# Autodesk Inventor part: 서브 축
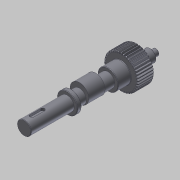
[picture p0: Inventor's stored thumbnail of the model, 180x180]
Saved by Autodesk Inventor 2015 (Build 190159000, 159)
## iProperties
Created: 2016-02
Part Number: 서브 축
Material: 강철, 연강
Document SubType Name: Modeling
Designer: mdu
Categories: <?xml version="1.0" encoding="UTF-16"?> <MemberInstance><Categories><FamilyTemplate><FamilyTemplateParameter ValueType="xs:double" Id="1" ObjectReferenceKey="da
Density: 7.86 g/cm^3
Mass: 504.229 g
Surface Area: 165.255 cm^2
Volume: 64.1512 cm^3
Appearance: 강철
CustomPartVersion: 1
Author: mdu
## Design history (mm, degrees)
sketch "Sketch1"
  geometry: C1 r 21 at (0, 0)
  constraints: 1 centre point
  dimensions: "d0" = 42 diameter of C1 (= da_da)
extrude "Extrusion1" new body sketch "Sketch1" distance "d1" = 20 (= da_b); taper "d2" = 0 deg
workplane "Work Plane2"
feature "피치 지름" dims "d4" = 10, "d5" = 0
workplane "Work Plane8"
workplane "Work Plane9"
chamfer "모따기1" distance "d49" = 1; stored, may be unused: second distance "d50" = 2, angle "d51" = 45 deg
sketch "스케치3"
  geometry: C1 r 12.5 at (0, 0); 1 further point
  constraints: 1 centre point, 1 coincident
  dimensions: "d52" = 25 diameter of C1
extrude "돌출2" join sketch "스케치3" distance "d53" = 16; taper "d54" = 0 deg
sketch "스케치4"
  geometry: C1 r 8.5 at (0, 0); 1 further point
  constraints: 1 centre point, 1 coincident
  dimensions: "d55" = 17 diameter of C1
extrude "돌출3" join sketch "스케치4" distance "d56" = 103; taper "d57" = 0 deg
sketch "스케치5"
  geometry: C1 r 7.5 at (0, 0); 1 further point
  constraints: 1 centre point, 1 coincident
  dimensions: "d62" = 15 diameter of C1
extrude "돌출4" join sketch "스케치5" distance "d63" = 16; taper "d64" = 0 deg
sketch "스케치6"
  geometry: C1 r 4 at (0, 0); 1 further point
  constraints: 1 centre point, 1 coincident
  dimensions: "d65" = 8 diameter of C1
extrude "돌출5" join sketch "스케치6" distance "d66" = 7; taper "d67" = 0 deg
chamfer "모따기2" distance "d58" = 0.5; stored, may be unused: second distance "d59" = 2, angle "d60" = 45 deg
fillet "모깎기1" dims "d61" = 0.5
feature "스퍼 기어" dims "da_b" = 20, "da_d" = 40, "da_aw" = 31, "da_da" = 42, "da_df" = 37.5, "da_dw" = 40, angle "da_beta" = 0 deg, "da_lefttooth" = 0, "da_righttooth" = 0
node "작업 평면11"
sketch "스케치7"
  geometry: C1 r 8.5 at (0, 0) reference; C2 r 11.5 at (0, 3); 1 further point
  constraints: 1 centre point, 1 tangent, 1 vertical alignment
  dimensions: "d71" = 3 distance of C2.centre point (0, 0); "d72" = 23 diameter of C2 (derived)
extrude "돌출6" join sketch "스케치7" stored distance "d73" = 20; taper "d74" = 0 deg
node "작업 평면12"
sketch "스케치8"
  geometry: C1 r 12.5 at (0, 0) reference; 1 further point
extrude "돌출7" join sketch "스케치8" distance "d76" = 5; taper "d77" = 0 deg
chamfer "모따기3" distance "d78" = 0.5; stored, may be unused: second distance "d79" = 2, angle "d80" = 45 deg
sketch "스케치9"
  geometry: L1 (-8.5, 86)-(-8.5, 138.5) reference; L2 (-8, 139)-(8, 139) reference; L3 (0, 0)-(0, 139); L4 (-8.5, 115)-(0, 115); L5 (-8.5, 115)-(-8.5, 113.5); L6 (-7, 115)-(-8.5, 113.5)
  constraints: 8 end point, 4 point on line, 1 midpoint, 1 perpendicular
  dimensions: "d81" = 24 distance between parallel lines of L2 L4; "d82" = 45 deg angle of L6 L5; "d83" = 3 diameter of L5.end L4
revolve "회전1" sketch "스케치9" stored, may be unused: angle "d84" = 90 deg
sketch "스케치10"
  geometry: L1 (-8.5, 113.5)-(-7, 115) reference; L2 (-8.5, 116.5)-(-7, 115) reference; 2 further points
  constraints: 1 coincident
node "작업점1"
node "작업 평면14"
sketch "스케치11"
  geometry: L1 (8.5, 102.5)-(-8.5, 102.5) reference; L2 (0, 102.5)-(0, -36); L3 (-2.5, 93.5)-(-2.5, 80.5); L4 (2.5, 80.5)-(2.5, 93.5); L5 (-8, 103)-(8, 103) reference; A1 r 2.5 centre (0, 93.5) between (2.5, 93.5) and (-2.5, 93.5); A2 r 2.5 centre (0, 80.5) between (-2.5, 80.5) and (2.5, 80.5)
  constraints: 6 end point, 4 point on circle, 4 tangent, 2 centre point, 1 midpoint, 1 parallel, 1 perpendicular, 1 point on line, 1 vertical alignment
  dimensions: "d85" = 7 distance edge to line of A1 L5; "d86" = 18 dimension on A2 A1; "d87" = 5 distance between parallel lines of L3 L4
extrude "돌출8" cut sketch "스케치11" distance "d88" = 3; taper "d89" = 0 deg
body "Solid1"
sketch "Sketch2"
  geometry: C1 r 21 at (0, 0) reference; C2 r 20 at (0, 0)
  constraints: 1 centre point, 1 coincident
  dimensions: "d3" = 40 diameter of C2 (= da_dw)
body "Srf1"
other parameters: "d16" = 31 (= da_aw), "d17" = 0, "d34" = 4.5 deg (computed from da_z), "d39" = 0, "d41" = 0, "d43" = 31 (= da_aw), "d46" = 31 (= da_aw), "d47" = 0, "d48" = 0, "d68" = 25
